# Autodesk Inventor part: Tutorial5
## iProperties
Created: 2009-05
Part Number: Tutorial5
Document SubType Name: Modeling
Designer: Sham
Density: 1 g/cm^3
Author: Sham
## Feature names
1. Mirror1
2. Split1
3. Fillet1
